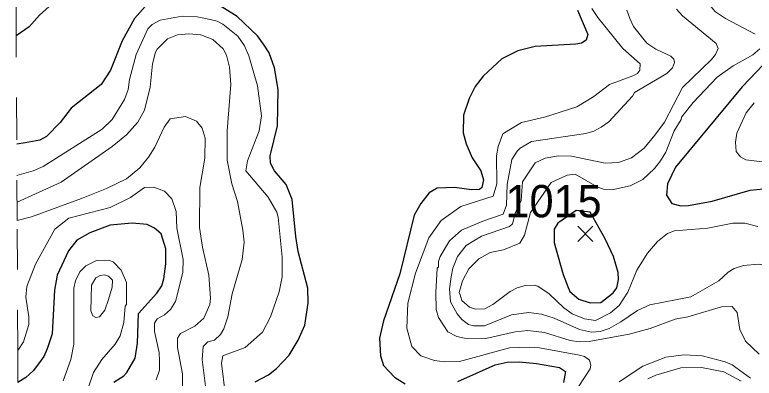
# Model space of a CAD drawing. Extents: x 423 to 448.8, y 7456.3 to 7484.
# Drawn here: x 423.009 to 424.838, y 7479.378 to 7480.278 of the extents above; entities that cross this region are included whole.
import ezdxf
from ezdxf.enums import TextEntityAlignment as Align

# ---------------------------------------------------------------- set-up
doc = ezdxf.new("R2010")
doc.units = 0
doc.header["$LTSCALE"] = 0.032
doc.linetypes.add('SHORT_DASHED', pattern=[2.7, 1.5, -1.2])
for name, color, linetype, lineweight in [('1', 7, 'Continuous', 25), ('2', 7, 'Continuous', 13), ('21', 7, 'Continuous', 25), ('22', 7, 'SHORT_DASHED', 13)]:
    doc.layers.add(name, color=color, linetype=linetype, lineweight=lineweight)
doc.layers.add('61', color=7, linetype='Continuous')

msp = doc.modelspace()

# ---------------------------------------------------------------- linework, layer by layer
at = {"layer": '1'}
for points in [[(423.0101, 7480.5952), (423.0681, 7480.578), (423.0929, 7480.5648), (423.1021, 7480.5517), (423.1276, 7480.4968), (423.1385, 7480.4086), (423.1315, 7480.356), (423.1168, 7480.3205), (423.0696, 7480.2771), (423.0441, 7480.2485), (423.012, 7480.2258)], [(423.6095, 7480.2261), (423.5585, 7480.274), (423.5214, 7480.2972), (423.4301, 7480.3344), (423.3875, 7480.3382), (423.3636, 7480.3289), (423.3442, 7480.3135), (423.3048, 7480.2694), (423.2738, 7480.2137), (423.2452, 7480.141), (423.222, 7480.1054), (423.1477, 7480.0467), (423.1207, 7480.0118), (423.0866, 7479.977), (423.0704, 7479.9678), (423.0341, 7479.9616), (423.0134, 7479.9582)], [(424.4007, 7480.2895), (424.4263, 7480.2292), (424.4224, 7480.2153), (424.4108, 7480.2083), (424.3969, 7480.2052), (424.2964, 7480.1998), (424.2531, 7480.189), (424.2136, 7480.1696), (424.1672, 7480.1263), (424.1478, 7480.1008), (424.1332, 7480.0714), (424.1185, 7480.0296), (424.1177, 7479.9863), (424.1254, 7479.9585), (424.1401, 7479.9237), (424.1618, 7479.892), (424.1687, 7479.8695), (424.1641, 7479.8509), (424.1587, 7479.8455), (424.1386, 7479.8447), (424.0968, 7479.8502), (424.0535, 7479.8486), (424.0341, 7479.837), (424.0132, 7479.8107), (423.997, 7479.7821), (423.9614, 7479.6367), (423.9205, 7479.5207)], [(423.6034, 7479.3691), (423.6366, 7479.3869), (423.6559, 7479.4024), (423.6876, 7479.4356), (423.7101, 7479.4727), (423.7263, 7479.5099), (423.7348, 7479.564), (423.7333, 7479.6011), (423.7101, 7479.6924), (423.7039, 7479.7295), (423.6946, 7479.8208), (423.6799, 7479.8579), (423.6513, 7479.892), (423.6412, 7479.9105), (423.6405, 7479.9291), (423.6583, 7480.0033), (423.6606, 7480.0931), (423.6513, 7480.1472), (423.6381, 7480.1843), (423.6257, 7480.2029), (423.6095, 7480.2261)], [(424.8609, 7480.1549), (424.8084, 7480.1), (424.6436, 7479.9012), (424.6235, 7479.8595), (424.6212, 7479.8316), (424.6343, 7479.8107), (424.6568, 7479.8053), (424.6754, 7479.8061), (424.7341, 7479.8169), (424.8285, 7479.844), (424.8857, 7479.8494)], [(423.2537, 7479.3683), (423.2785, 7479.3845), (423.2854, 7479.3923), (423.3063, 7479.4279), (423.3125, 7479.465), (423.3148, 7479.5385), (423.3597, 7479.5888), (423.372, 7479.6073), (423.3775, 7479.6243), (423.3821, 7479.6615), (423.3821, 7479.6986), (423.3705, 7479.7357), (423.3543, 7479.7496), (423.3357, 7479.7589), (423.2986, 7479.762), (423.2445, 7479.7574), (423.1942, 7479.738), (423.1624, 7479.7203), (423.1416, 7479.694), (423.113, 7479.6336), (423.1068, 7479.5965), (423.1006, 7479.4882), (423.089, 7479.4511), (423.0805, 7479.4325), (423.0673, 7479.414), (423.0542, 7479.3969), (423.0356, 7479.3799), (423.0163, 7479.3681)], [(423.9205, 7479.5207), (423.9112, 7479.4774), (423.9135, 7479.4341), (423.9212, 7479.4101), (423.9483, 7479.3807), (423.9746, 7479.3645)], [(424.1046, 7479.3706), (424.1974, 7479.4116), (424.2268, 7479.4178), (424.2562, 7479.4186), (424.2995, 7479.4147), (424.3567, 7479.4047), (424.3714, 7479.3946), (424.366, 7479.3676)]]:
    msp.add_lwpolyline(points, dxfattribs=at)
msp.add_lwpolyline([(424.4897, 7479.68), (424.4696, 7479.7234), (424.4326, 7479.7895), (424.3977, 7479.7936), (424.352, 7479.7626), (424.343, 7479.7477), (424.343, 7479.7316), (424.3435, 7479.7148), (424.3466, 7479.7017), (424.3652, 7479.6352), (424.3775, 7479.6027), (424.3822, 7479.5934), (424.4039, 7479.5741), (424.4325, 7479.5648), (424.4588, 7479.5656), (424.4889, 7479.5895), (424.4982, 7479.6019), (424.5021, 7479.6228), (424.5013, 7479.6398)], close=True, dxfattribs=at)
at = {"layer": '2'}
for points in [[(424.8409, 7480.2299), (424.7674, 7480.2694), (424.7426, 7480.2856), (424.7349, 7480.2942), (424.7194, 7480.3158), (424.7001, 7480.3576), (424.6885, 7480.387), (424.68, 7480.421), (424.6491, 7480.4829), (424.6158, 7480.5239), (424.5323, 7480.5974), (424.5044, 7480.6383), (424.4882, 7480.6747)], [(424.4363, 7480.2942), (424.451, 7480.2717), (424.5129, 7480.1952), (424.5562, 7480.1572), (424.5554, 7480.141), (424.5493, 7480.1332), (424.5377, 7480.1271), (424.4805, 7480.1054), (424.441, 7480.076), (424.3992, 7480.0505), (424.3196, 7480.025), (424.2623, 7480.0118), (424.2159, 7479.9832), (424.2043, 7479.9523), (424.2005, 7479.9291), (424.2012, 7479.8595), (424.1919, 7479.8293), (424.1123, 7479.8038), (424.0635, 7479.769), (424.0334, 7479.7256), (424.0001, 7479.6383), (423.9808, 7479.564), (423.9784, 7479.5021), (423.9908, 7479.4565), (424.0132, 7479.434), (424.0473, 7479.4224), (424.0721, 7479.4186), (424.1092, 7479.4201), (424.2329, 7479.4534), (424.2824, 7479.4549), (424.3072, 7479.4534), (424.4062, 7479.4356), (424.4186, 7479.4325), (424.431, 7479.4232), (424.434, 7479.4109), (424.4325, 7479.4015), (424.3482, 7479.2732)], [(424.8501, 7479.4379), (424.8169, 7479.4697), (424.803, 7479.499), (424.796, 7479.5408), (424.7837, 7479.5562), (424.7574, 7479.5555), (424.6738, 7479.5307), (424.6429, 7479.5245), (424.581, 7479.5013), (424.5284, 7479.4874), (424.434, 7479.4704), (424.4047, 7479.4688), (424.383, 7479.4719), (424.3196, 7479.4913), (424.2778, 7479.4967), (424.2469, 7479.4936), (424.1742, 7479.4766), (424.1216, 7479.4774), (424.1022, 7479.482), (424.0798, 7479.4929), (424.0566, 7479.5284), (424.0512, 7479.5485), (424.0504, 7479.5903), (424.0535, 7479.6506), (424.0566, 7479.6545), (424.0566, 7479.6677), (424.0612, 7479.68), (424.0844, 7479.7187), (424.1138, 7479.745), (424.1664, 7479.7674), (424.2174, 7479.7844), (424.2252, 7479.8069), (424.2267, 7479.8579), (424.2383, 7479.9198), (424.2515, 7479.9407), (424.2592, 7479.9476), (424.2871, 7479.9647), (424.4217, 7479.9847), (424.441, 7479.9902), (424.4596, 7480.0002), (424.4781, 7480.0134), (424.5369, 7480.0768), (424.5423, 7480.0861), (424.622, 7480.1332), (424.6359, 7480.1472), (424.6413, 7480.1603), (424.639, 7480.1681), (424.6321, 7480.1758), (424.5949, 7480.1928), (424.5725, 7480.2083), (424.5392, 7480.2493), (424.5307, 7480.2694), (424.523, 7480.2895)], [(424.7736, 7479.6406), (424.7504, 7479.6197), (424.6816, 7479.5795), (424.5802, 7479.5601), (424.5493, 7479.5462), (424.5083, 7479.5176), (424.4789, 7479.5013), (424.4573, 7479.4944), (424.4356, 7479.4928), (424.4062, 7479.499), (424.3428, 7479.5269), (424.3118, 7479.5369), (424.2794, 7479.5408), (424.2376, 7479.5354), (424.1711, 7479.5083), (424.1432, 7479.5083), (424.1316, 7479.5114), (424.1146, 7479.5238), (424.103, 7479.5377), (424.0867, 7479.5671), (424.0844, 7479.5996), (424.0883, 7479.629), (424.0922, 7479.6506), (424.1037, 7479.68), (424.1254, 7479.7071), (424.1633, 7479.7303), (424.2329, 7479.7543), (424.2399, 7479.7605), (424.2476, 7479.7891), (424.2616, 7479.8185), (424.2646, 7479.8649), (424.2964, 7479.912), (424.3211, 7479.9236), (424.3536, 7479.9291), (424.3861, 7479.9283), (424.4696, 7479.9105), (424.5021, 7479.9128), (424.5346, 7479.9244), (424.5663, 7479.9477), (424.5926, 7479.9801), (424.6158, 7480.0126), (424.6606, 7480.0984), (424.7326, 7480.1673), (424.7423, 7480.1803), (424.7488, 7480.1952), (424.7442, 7480.2075), (424.6607, 7480.2756), (424.6459, 7480.2926)], [(423.5291, 7479.3413), (423.5198, 7479.4155), (423.5237, 7479.434), (423.5786, 7479.4541), (423.6211, 7479.4921), (423.6412, 7479.53), (423.6629, 7479.5919), (423.6699, 7479.629), (423.6699, 7479.6785), (423.6606, 7479.7775), (423.6567, 7479.7899), (423.6358, 7479.827), (423.5801, 7479.892), (423.584, 7479.9167), (423.6134, 7479.991), (423.6188, 7480.0281), (423.6087, 7480.1023), (423.5879, 7480.1766), (423.577, 7480.2013), (423.5608, 7480.2253), (423.5229, 7480.2547), (423.509, 7480.2624), (423.4842, 7480.2686), (423.4595, 7480.2732), (423.4224, 7480.2748), (423.3682, 7480.2647), (423.3481, 7480.2539), (423.338, 7480.2439), (423.3086, 7480.1797), (423.2924, 7480.1178), (423.2893, 7480.0931), (423.28, 7480.0683), (423.2491, 7480.0188), (423.2251, 7479.9948), (423.0789, 7479.9028), (423.0542, 7479.8919), (423.0138, 7479.8803)], [(423.0141, 7479.8144), (423.123, 7479.8641), (423.2491, 7479.9522), (423.2847, 7479.9809), (423.3133, 7480.0126), (423.3295, 7480.042), (423.3435, 7480.0993), (423.3496, 7480.1565), (423.3566, 7480.1859), (423.3612, 7480.1928), (423.3867, 7480.2184), (423.4115, 7480.2284), (423.4394, 7480.2315), (423.4688, 7480.2284), (423.4982, 7480.2168), (423.5244, 7480.1936), (423.5322, 7480.1781), (423.5399, 7480.1488), (423.543, 7480.1054), (423.5337, 7479.991), (423.5337, 7479.9183), (423.5453, 7479.8595), (423.5592, 7479.8162), (423.5732, 7479.745), (423.5762, 7479.7156), (423.5709, 7479.6723), (423.5461, 7479.5872), (423.5353, 7479.53), (423.526, 7479.5006), (423.5175, 7479.4867), (423.5028, 7479.4727), (423.4858, 7479.4681), (423.4749, 7479.4565), (423.4719, 7479.4248), (423.4811, 7479.3521)], [(424.8471, 7479.7543), (424.8146, 7479.762), (424.7852, 7479.762), (424.7233, 7479.7496), (424.6413, 7479.7435), (424.6235, 7479.7365), (424.5988, 7479.7171), (424.574, 7479.6878), (424.5477, 7479.646), (424.5253, 7479.5911), (424.5044, 7479.5586), (424.4827, 7479.54), (424.4456, 7479.5215), (424.4186, 7479.5253), (424.3876, 7479.5377), (424.3667, 7479.5524), (424.3311, 7479.5872), (424.3026, 7479.6065), (424.2933, 7479.6089), (424.2716, 7479.6081), (424.2515, 7479.6019), (424.2344, 7479.5934), (424.1912, 7479.5609), (424.1718, 7479.5501), (424.1486, 7479.5493), (424.1339, 7479.5547), (424.1146, 7479.571), (424.1107, 7479.5849), (424.1084, 7479.5903), (424.1161, 7479.6197), (424.1324, 7479.6491), (424.1564, 7479.6738), (424.185, 7479.6893), (424.2175, 7479.6962), (424.2584, 7479.7125), (424.2701, 7479.7326), (424.2848, 7479.7884), (424.3358, 7479.8626), (424.3753, 7479.8811), (424.3954, 7479.8834), (424.4495, 7479.8525), (424.465, 7479.8463), (424.4897, 7479.8456), (424.5315, 7479.8548), (424.5624, 7479.8703), (424.5918, 7479.8974), (424.6065, 7479.9167), (424.6197, 7479.9384), (424.6405, 7479.991), (424.6575, 7480.0188), (424.6583, 7480.025), (424.6869, 7480.0613), (424.7465, 7480.124), (424.7859, 7480.1518), (424.8161, 7480.1681), (424.8347, 7480.1789), (424.8517, 7480.1936)], [(424.8385, 7480.0606), (424.8184, 7480.0358), (424.7952, 7479.9848), (424.7921, 7479.9631), (424.7937, 7479.9399), (424.8045, 7479.9268), (424.8177, 7479.919), (424.9198, 7479.9066)], [(423.0143, 7479.7688), (423.0496, 7479.7782), (423.1733, 7479.8231), (423.2352, 7479.8478), (423.2847, 7479.8718), (423.3179, 7479.8997), (423.3396, 7479.926), (423.355, 7479.9507), (423.3782, 7480.0002), (423.393, 7480.0204), (423.4308, 7480.0265), (423.4579, 7480.0149), (423.4718, 7479.9972), (423.4796, 7479.9724), (423.4788, 7479.9229), (423.4664, 7479.8502), (423.4657, 7479.7512), (423.4726, 7479.7032), (423.4889, 7479.6336), (423.4927, 7479.5764), (423.4912, 7479.5609), (423.4765, 7479.5268), (423.454, 7479.5075), (423.4185, 7479.489), (423.4115, 7479.4774), (423.4115, 7479.4542), (423.4239, 7479.3892), (423.4239, 7479.3583)], [(423.0159, 7479.4473), (423.0302, 7479.4681), (423.0434, 7479.5114), (423.0434, 7479.53), (423.0356, 7479.5787), (423.0387, 7479.6058), (423.0596, 7479.6607), (423.1075, 7479.7473), (423.1424, 7479.7744), (423.2445, 7479.8014), (423.2947, 7479.8262), (423.3295, 7479.8509), (423.3527, 7479.8517), (423.379, 7479.8417), (423.3968, 7479.8224), (423.4076, 7479.7914), (423.4092, 7479.7496), (423.4254, 7479.6723), (423.4246, 7479.6398), (423.4061, 7479.5687), (423.3937, 7479.5485), (423.379, 7479.5354), (423.3612, 7479.5253), (423.3543, 7479.5145), (423.3543, 7479.4944), (423.3659, 7479.4418), (423.3667, 7479.4202), (423.3667, 7479.3985), (423.3581, 7479.3745)], [(423.1284, 7479.3722), (423.147, 7479.4248), (423.1547, 7479.4627), (423.1547, 7479.6011), (423.1586, 7479.6197), (423.1694, 7479.6421), (423.1841, 7479.6568), (423.2104, 7479.6699), (423.2421, 7479.6707), (423.2529, 7479.6661), (423.2715, 7479.646), (423.2847, 7479.6151), (423.2847, 7479.5609), (423.2816, 7479.557), (423.2785, 7479.5161), (423.2692, 7479.4836), (423.2568, 7479.4627), (423.2235, 7479.4248), (423.2034, 7479.3923), (423.1903, 7479.3536)], [(425.0365, 7479.3289), (425.0056, 7479.4232), (424.9754, 7479.4774), (424.9484, 7479.5067), (424.9027, 7479.5315), (424.8764, 7479.5524), (424.8672, 7479.5686), (424.8641, 7479.5934), (424.8734, 7479.6336), (424.8734, 7479.6445), (424.8672, 7479.6545), (424.8625, 7479.6583), (424.8486, 7479.6607), (424.8114, 7479.6576), (424.789, 7479.6499), (424.7736, 7479.6406)], [(424.5037, 7479.3691), (424.5624, 7479.4085), (424.6197, 7479.4302), (424.6645, 7479.4364), (424.7094, 7479.434), (424.7666, 7479.4193), (424.7836, 7479.4116), (424.8293, 7479.3783)], [(424.5748, 7479.3768), (424.5949, 7479.3861), (424.6568, 7479.4039), (424.7079, 7479.4047), (424.7627, 7479.3939), (424.8061, 7479.3714)]]:
    msp.add_lwpolyline(points, dxfattribs=at)
msp.add_lwpolyline([(423.2405, 7479.5733), (423.2498, 7479.6042), (423.2506, 7479.6212), (423.2406, 7479.6313), (423.2305, 7479.6344), (423.2197, 7479.6328), (423.2089, 7479.6267), (423.198, 7479.6089), (423.1965, 7479.5455), (423.2019, 7479.533), (423.2088, 7479.5284), (423.2182, 7479.5307), (423.2313, 7479.547)], close=True, dxfattribs=at)
at = {"layer": '21'}
for p, q in [((424.4014, 7479.7546), (424.4389, 7479.7171)), ((424.4389, 7479.7546), (424.4014, 7479.7171))]:
    msp.add_line(p, q, dxfattribs=at)
at = {"layer": '22'}
for points in [[(423.012, 7480.2258), (423.0104, 7480.538), (423.0101, 7480.5952), (423.0091, 7480.7865), (423.0089, 7480.8296), (423.0085, 7480.9007)], [(423.0143, 7479.7688), (423.0133, 7479.9732), (423.012, 7480.2258)], [(423.0163, 7479.3681), (423.0161, 7479.4084), (423.0159, 7479.4473), (423.0143, 7479.7688)]]:
    msp.add_lwpolyline(points, dxfattribs=at)

# ---------------------------------------------------------------- texts
at = {"layer": '61'}
msp.add_text('1015', height=0.08, dxfattribs=at).set_placement((424.3417, 7479.7768), align=Align.CENTER)

doc.saveas('drawing.dxf')
